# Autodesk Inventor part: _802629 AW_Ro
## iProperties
Shininess: 64.0
Length Units: 11269
Angle Units: 11279
Time Units: 11290
Mass Units: 11283
Length Display Precision: 3
Angle Display Precision: 2
Compacted: True
Part Number: _802629 AW_Ro
Document SubType Name: Blech
Created: 2003-07
Material: Standard
Designer: achiml
Density: 0.0
Volumn: 0.0
Area: 0.0
PropertySet Name: Model Information
Control State: 0
Master: False
Checked Out: False
Author: achiml
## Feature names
1. Extrusion1
2. ExtrusionAbwicklung1
